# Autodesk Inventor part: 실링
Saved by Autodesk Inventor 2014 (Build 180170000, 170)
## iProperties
Created: 2026-09
Part Number: 실링
Material: 고무
Document SubType Name: Modeling
Designer: dg
Density: 0.93 g/cm^3
Appearance: 고무 - 검은색 - 버전 1.1
Mass: 1.89521 g
Surface Area: 24.4476 cm^2
Volume: 2.03786 cm^3
Author: jhkim
Creation Date: 2026-08-26
Sending System: Autodesk Inventor 2027
Preprocessor: ST-DEVELOPER v20.1
Author: dg
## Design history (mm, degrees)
node "실링1"
node "솔리드3"
node "기준1"
